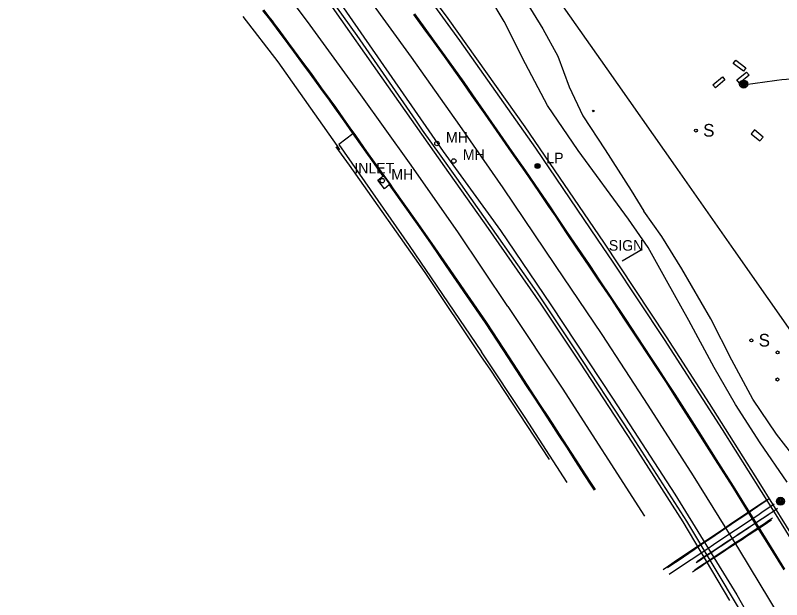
# Model space of a CAD drawing. Extents: x 368532 to 392481, y 10654822 to 10676899.
# Drawn here: x 370545.2 to 370907.9, y 10674120.6 to 10674397.3 of the extents above; entities that cross this region are included whole.
import ezdxf

# ---------------------------------------------------------------- set-up
doc = ezdxf.new("R2010")
doc.units = 0
for name, color, linetype in [('p_Catenary', 7, 'Continuous'), ('p_drainage inlet', 7, 'Continuous'), ('p_dtm sidewalk', 7, 'Continuous'), ('p_railroad rr control', 7, 'Continuous'), ('p_road - paved curb', 7, 'Continuous'), ('p_road conc barrier', 7, 'Continuous'), ('p_road dirt road', 7, 'Continuous'), ('p_road guard rails', 7, 'Continuous'), ('p_road paint stripe', 7, 'Continuous'), ('p_structure sign', 7, 'Continuous'), ('p_structure unidentified', 7, 'Continuous'), ('p_utility general pole', 7, 'Continuous'), ('p_utility manhole', 7, 'Continuous')]:
    doc.layers.add(name, color=color, linetype=linetype)

msp = doc.modelspace()

# ---------------------------------------------------------------- linework, layer by layer
at = {"layer": 'p_Catenary'}
for points in [[(370889.62, 10674364.43), (370891.92, 10674364.73), (370894.21, 10674365.03), (370896.51, 10674365.34), (370898.8, 10674365.64), (370901.1, 10674365.94), (370903.39, 10674366.25), (370905.69, 10674366.55), (370907.98, 10674366.85), (370910.28, 10674367.16), (370912.57, 10674367.46), (370914.87, 10674367.76), (370917.17, 10674368.07), (370919.46, 10674368.37), (370921.76, 10674368.67), (370924.05, 10674368.98), (370926.35, 10674369.28), (370928.64, 10674369.58), (370930.94, 10674369.89), (370933.23, 10674370.19)], [(370851.8, 10674134.93), (370854.4, 10674136.69), (370857.01, 10674138.44), (370859.61, 10674140.19), (370862.22, 10674141.95), (370864.82, 10674143.7), (370867.43, 10674145.45), (370870.03, 10674147.21), (370872.64, 10674148.96), (370875.24, 10674150.72), (370877.85, 10674152.47), (370880.45, 10674154.22), (370883.06, 10674155.98), (370885.67, 10674157.73), (370888.27, 10674159.48), (370890.88, 10674161.24), (370893.48, 10674162.99), (370896.09, 10674164.74), (370898.69, 10674166.5), (370901.3, 10674168.25)], [(370853.83, 10674135.81), (370856.35, 10674137.52), (370858.87, 10674139.22), (370861.39, 10674140.93), (370863.91, 10674142.64), (370866.43, 10674144.35), (370868.95, 10674146.05), (370871.47, 10674147.76), (370874, 10674149.47), (370876.52, 10674151.18), (370879.04, 10674152.88), (370881.56, 10674154.59), (370884.08, 10674156.3), (370886.6, 10674158.01), (370889.12, 10674159.71), (370891.64, 10674161.42), (370894.16, 10674163.13), (370896.68, 10674164.84), (370899.2, 10674166.54), (370901.72, 10674168.25)], [(370854.6, 10674132.63), (370857.22, 10674134.38), (370859.85, 10674136.13), (370862.47, 10674137.89), (370865.09, 10674139.64), (370867.72, 10674141.39), (370870.34, 10674143.15), (370872.96, 10674144.9), (370875.59, 10674146.65), (370878.21, 10674148.41), (370880.84, 10674150.16), (370883.46, 10674151.91), (370886.08, 10674153.67), (370888.71, 10674155.42), (370891.33, 10674157.17), (370893.95, 10674158.92), (370896.58, 10674160.68), (370899.2, 10674162.43), (370901.83, 10674164.18), (370904.45, 10674165.94)], [(370867.41, 10674138.2), (370869.44, 10674139.54), (370871.46, 10674140.88), (370873.48, 10674142.22), (370875.5, 10674143.57), (370877.53, 10674144.91), (370879.55, 10674146.25), (370881.57, 10674147.59), (370883.59, 10674148.94), (370885.61, 10674150.28), (370887.64, 10674151.62), (370889.66, 10674152.96), (370891.68, 10674154.31), (370893.7, 10674155.65), (370895.73, 10674156.99), (370897.75, 10674158.33), (370899.77, 10674159.68), (370901.79, 10674161.02), (370903.82, 10674162.36), (370905.84, 10674163.7)], [(370867.72, 10674138.62), (370869.74, 10674139.95), (370871.75, 10674141.28), (370873.77, 10674142.61), (370875.78, 10674143.94), (370877.8, 10674145.27), (370879.81, 10674146.6), (370881.83, 10674147.93), (370883.84, 10674149.25), (370885.86, 10674150.58), (370887.88, 10674151.91), (370889.89, 10674153.24), (370891.91, 10674154.57), (370893.92, 10674155.9), (370895.94, 10674157.23), (370897.95, 10674158.56), (370899.97, 10674159.89), (370901.99, 10674161.22), (370904, 10674162.55), (370906.02, 10674163.88)], [(370866.64, 10674134.64), (370868.59, 10674135.94), (370870.53, 10674137.24), (370872.48, 10674138.54), (370874.43, 10674139.84), (370876.37, 10674141.14), (370878.32, 10674142.44), (370880.27, 10674143.74), (370882.21, 10674145.04), (370884.16, 10674146.34), (370886.11, 10674147.64), (370888.05, 10674148.94), (370890, 10674150.24), (370891.95, 10674151.53), (370893.89, 10674152.83), (370895.84, 10674154.13), (370897.79, 10674155.43), (370899.73, 10674156.73), (370901.68, 10674158.03), (370903.63, 10674159.33)], [(370865.72, 10674133.76), (370867.69, 10674135.05), (370869.66, 10674136.35), (370871.63, 10674137.65), (370873.6, 10674138.94), (370875.57, 10674140.24), (370877.54, 10674141.53), (370879.51, 10674142.83), (370881.48, 10674144.12), (370883.45, 10674145.42), (370885.42, 10674146.71), (370887.39, 10674148.01), (370889.35, 10674149.3), (370891.32, 10674150.6), (370893.29, 10674151.9), (370895.26, 10674153.19), (370897.23, 10674154.49), (370899.2, 10674155.78), (370901.17, 10674157.08), (370903.14, 10674158.37)]]:
    msp.add_lwpolyline(points, dxfattribs=at)
at = {"layer": 'p_drainage inlet'}
for p, q in [((370716.82, 10674319.32), (370719.2, 10674321.11)), ((370719.86, 10674315.21), (370716.82, 10674319.32)), ((370719.2, 10674321.11), (370719.49, 10674321.31)), ((370719.49, 10674321.31), (370719.61, 10674321.4)), ((370719.49, 10674321.31), (370722.4, 10674317.26)), ((370722.12, 10674317.06), (370719.86, 10674315.21)), ((370722.4, 10674317.26), (370722.12, 10674317.06)), ((370722.4, 10674317.26), (370722.53, 10674317.35))]:
    msp.add_line(p, q, dxfattribs=at)
at = {"layer": 'p_dtm sidewalk'}
for p, q in [((370755.52, 10674385.45), (370717.25, 10674438.01)), ((370791.51, 10674334.39), (370755.52, 10674385.45)), ((370704.96, 10674341.16), (370698.28, 10674336.12)), ((370698.28, 10674336.12), (370731.66, 10674288.32)), ((370820.7, 10674291.32), (370791.51, 10674334.39)), ((370828.14, 10674280.38), (370820.7, 10674291.32)), ((370731.66, 10674288.32), (370765.85, 10674237.98)), ((370852.51, 10674243.75), (370828.14, 10674280.38)), ((370879.96, 10674201.22), (370852.51, 10674243.75)), ((370786.47, 10674206.89), (370765.85, 10674237.98)), ((370806.46, 10674176.11), (370786.47, 10674206.89)), ((370904.59, 10674162.07), (370879.96, 10674201.22)), ((370927.33, 10674124.84), (370904.59, 10674162.07))]:
    msp.add_line(p, q, dxfattribs=at)
at = {"layer": 'p_railroad rr control'}
for points in [[(370857.7, 10674325.96), (370825.29, 10674372.03), (370785.06, 10674429.25), (370743.67, 10674488.23), (370705.22, 10674542.98), (370668.52, 10674595.11), (370628.47, 10674651.67), (370587.92, 10674709.74), (370548.91, 10674764.7), (370545.17, 10674770.04)], [(371121.64, 10673939.77), (371094.86, 10673983.41), (371066.28, 10674027.4), (371041.68, 10674063.49), (371026.94, 10674085.12), (371005.22, 10674117.09), (370994.49, 10674132.1), (370964.03, 10674174.34), (370939.37, 10674209.22), (370917.74, 10674239.94), (370885.32, 10674286.37), (370857.7, 10674325.96)]]:
    msp.add_lwpolyline(points, dxfattribs=at)
at = {"layer": 'p_road - paved curb'}
for p, q in [((370698.05, 10674404.45), (370728.73, 10674360.2)), ((370662.21, 10674399.61), (370664.78, 10674396.32)), ((370662.48, 10674399.83), (370665.05, 10674396.54)), ((370662.6, 10674399.92), (370665.17, 10674396.63)), ((370718.75, 10674367.74), (370695.36, 10674401.2)), ((370664.78, 10674396.32), (370666.32, 10674394.36)), ((370665.05, 10674396.54), (370666.59, 10674394.58)), ((370665.17, 10674396.63), (370666.71, 10674394.67)), ((370666.71, 10674394.67), (370667.76, 10674393.34)), ((370738.85, 10674391.04), (370733.95, 10674397.86)), ((370739.14, 10674391.24), (370734.24, 10674398.06)), ((370666.32, 10674394.36), (370667.36, 10674393.04)), ((370666.59, 10674394.58), (370667.64, 10674393.25)), ((370667.36, 10674393.04), (370669.45, 10674390.19)), ((370667.64, 10674393.25), (370669.73, 10674390.4)), ((370667.76, 10674393.34), (370669.85, 10674390.49)), ((370743.32, 10674384.82), (370738.85, 10674391.04)), ((370743.61, 10674385.02), (370739.14, 10674391.24)), ((370669.45, 10674390.19), (370671.53, 10674387.37)), ((370669.73, 10674390.4), (370671.81, 10674387.58)), ((370669.85, 10674390.49), (370671.93, 10674387.67)), ((370671.81, 10674387.58), (370674.39, 10674384.08)), ((370671.93, 10674387.67), (370674.51, 10674384.17)), ((370671.53, 10674387.37), (370674.11, 10674383.87)), ((370674.11, 10674383.87), (370676.79, 10674380.19)), ((370674.39, 10674384.08), (370677.07, 10674380.39)), ((370674.51, 10674384.17), (370677.19, 10674380.48)), ((370748.37, 10674377.86), (370743.32, 10674384.82)), ((370748.66, 10674378.06), (370743.61, 10674385.02)), ((370676.79, 10674380.19), (370680.67, 10674374.9)), ((370677.07, 10674380.39), (370680.95, 10674375.11)), ((370677.19, 10674380.48), (370681.07, 10674375.2)), ((370757.33, 10674365.4), (370748.37, 10674377.86)), ((370757.62, 10674365.6), (370748.66, 10674378.06)), ((370680.67, 10674374.9), (370684.75, 10674369.39)), ((370680.95, 10674375.11), (370685.03, 10674369.6)), ((370681.07, 10674375.2), (370685.15, 10674369.69)), ((370684.75, 10674369.39), (370689.59, 10674362.74)), ((370685.03, 10674369.6), (370689.87, 10674362.95)), ((370685.15, 10674369.69), (370689.99, 10674363.04)), ((370748.51, 10674325.6), (370718.75, 10674367.74)), ((370689.59, 10674362.74), (370693.7, 10674357.18)), ((370689.87, 10674362.95), (370693.98, 10674357.38)), ((370689.99, 10674363.04), (370694.1, 10674357.47)), ((370761.43, 10674359.43), (370757.33, 10674365.4)), ((370761.72, 10674359.62), (370757.62, 10674365.6)), ((370728.73, 10674360.2), (370747.67, 10674332.82)), ((370767.63, 10674350.56), (370761.43, 10674359.43)), ((370767.92, 10674350.76), (370761.72, 10674359.62)), ((370693.7, 10674357.18), (370696.3, 10674353.51)), ((370693.98, 10674357.38), (370696.59, 10674353.71)), ((370694.1, 10674357.47), (370696.71, 10674353.8)), ((370696.3, 10674353.51), (370699.82, 10674348.49)), ((370696.59, 10674353.71), (370700.11, 10674348.69)), ((370696.71, 10674353.8), (370700.23, 10674348.78)), ((370699.82, 10674348.49), (370703.17, 10674343.79)), ((370700.11, 10674348.69), (370703.46, 10674343.99)), ((370700.23, 10674348.78), (370703.58, 10674344.08)), ((370774.44, 10674340.83), (370767.63, 10674350.56)), ((370774.73, 10674341.03), (370767.92, 10674350.76)), ((370703.46, 10674343.99), (370706.05, 10674340.3)), ((370703.58, 10674344.08), (370706.17, 10674340.39)), ((370703.17, 10674343.79), (370705.76, 10674340.1)), ((370706.05, 10674340.3), (370711.35, 10674332.74)), ((370706.17, 10674340.39), (370711.47, 10674332.83)), ((370780.09, 10674332.65), (370774.44, 10674340.83)), ((370780.38, 10674332.85), (370774.73, 10674341.03)), ((370705.76, 10674340.1), (370711.06, 10674332.54)), ((370711.06, 10674332.54), (370714.65, 10674327.49)), ((370711.35, 10674332.74), (370714.94, 10674327.69)), ((370711.47, 10674332.83), (370715.06, 10674327.78)), ((370747.67, 10674332.82), (370774.87, 10674295.39)), ((370786.58, 10674323.4), (370780.09, 10674332.65)), ((370786.87, 10674323.6), (370780.38, 10674332.85)), ((370714.65, 10674327.49), (370717.12, 10674324)), ((370714.94, 10674327.69), (370717.41, 10674324.2)), ((370715.06, 10674327.78), (370717.53, 10674324.29)), ((370717.12, 10674324), (370719.2, 10674321.11)), ((370717.41, 10674324.2), (370719.49, 10674321.31)), ((370717.53, 10674324.29), (370719.61, 10674321.4)), ((370769.1, 10674296.37), (370748.51, 10674325.6)), ((370793.07, 10674314.04), (370786.58, 10674323.4)), ((370793.36, 10674314.24), (370786.87, 10674323.6)), ((370719.61, 10674321.4), (370722.53, 10674317.35)), ((370722.12, 10674317.06), (370723.67, 10674314.9)), ((370722.4, 10674317.26), (370723.96, 10674315.1)), ((370722.53, 10674317.35), (370724.08, 10674315.19)), ((370723.67, 10674314.9), (370728.74, 10674307.74)), ((370723.96, 10674315.1), (370729.03, 10674307.94)), ((370724.08, 10674315.19), (370729.15, 10674308.03)), ((370797.85, 10674306.94), (370793.07, 10674314.04)), ((370798.14, 10674307.14), (370793.36, 10674314.24)), ((370728.74, 10674307.74), (370735.35, 10674298.39)), ((370729.03, 10674307.94), (370735.64, 10674298.59)), ((370729.15, 10674308.03), (370735.76, 10674298.68)), ((370800.91, 10674302.39), (370797.85, 10674306.94)), ((370801.21, 10674302.59), (370798.14, 10674307.14)), ((370806.25, 10674294.34), (370800.91, 10674302.39)), ((370806.54, 10674294.54), (370801.21, 10674302.59)), ((370735.35, 10674298.39), (370741.94, 10674288.91)), ((370735.64, 10674298.59), (370742.23, 10674289.1)), ((370735.76, 10674298.68), (370742.35, 10674289.19)), ((370794.14, 10674260.51), (370769.1, 10674296.37)), ((370774.87, 10674295.39), (370798.73, 10674260.18)), ((370811.11, 10674287.21), (370806.25, 10674294.34)), ((370811.4, 10674287.41), (370806.54, 10674294.54)), ((370741.94, 10674288.91), (370749.01, 10674278.68)), ((370742.23, 10674289.1), (370749.3, 10674278.87)), ((370742.35, 10674289.19), (370749.42, 10674278.96)), ((370816.96, 10674278.62), (370811.11, 10674287.21)), ((370817.25, 10674278.82), (370811.4, 10674287.41)), ((370749.01, 10674278.68), (370758.73, 10674264.55)), ((370749.3, 10674278.87), (370759.02, 10674264.75)), ((370749.42, 10674278.96), (370759.14, 10674264.83)), ((370821.42, 10674271.93), (370816.96, 10674278.62)), ((370821.72, 10674272.13), (370817.25, 10674278.82)), ((370827.3, 10674263.24), (370821.42, 10674271.93)), ((370827.6, 10674263.44), (370821.72, 10674272.13)), ((370758.73, 10674264.55), (370767.56, 10674251.65)), ((370759.02, 10674264.75), (370767.85, 10674251.85)), ((370759.14, 10674264.83), (370767.97, 10674251.93)), ((370812.34, 10674233.04), (370794.14, 10674260.51)), ((370833.68, 10674253.58), (370827.3, 10674263.24)), ((370833.97, 10674253.77), (370827.6, 10674263.44)), ((370798.73, 10674260.18), (370828.13, 10674215.49)), ((370839.36, 10674244.91), (370833.68, 10674253.58)), ((370839.65, 10674245.1), (370833.97, 10674253.77)), ((370767.56, 10674251.65), (370775.96, 10674238.97)), ((370767.85, 10674251.85), (370776.25, 10674239.16)), ((370767.97, 10674251.93), (370776.38, 10674239.24)), ((370845.75, 10674235.25), (370839.36, 10674244.91)), ((370846.04, 10674235.44), (370839.65, 10674245.1)), ((370775.96, 10674238.97), (370782.47, 10674228.93)), ((370776.25, 10674239.16), (370782.76, 10674229.12)), ((370776.38, 10674239.24), (370782.89, 10674229.2)), ((370848.81, 10674230.56), (370845.75, 10674235.25)), ((370849.1, 10674230.75), (370846.04, 10674235.44)), ((370837.55, 10674194.66), (370812.34, 10674233.04)), ((370782.47, 10674228.93), (370787.04, 10674221.9)), ((370782.76, 10674229.12), (370787.33, 10674222.09)), ((370782.89, 10674229.2), (370787.46, 10674222.17)), ((370853.49, 10674223.48), (370848.81, 10674230.56)), ((370853.78, 10674223.67), (370849.1, 10674230.75)), ((370787.04, 10674221.9), (370790.54, 10674216.54)), ((370787.33, 10674222.09), (370790.83, 10674216.73)), ((370787.46, 10674222.17), (370790.96, 10674216.81)), ((370857.2, 10674217.65), (370853.49, 10674223.48)), ((370857.49, 10674217.84), (370853.78, 10674223.67)), ((370868.52, 10674199.82), (370857.2, 10674217.65)), ((370868.81, 10674200.01), (370857.49, 10674217.84)), ((370790.54, 10674216.54), (370793.58, 10674211.92)), ((370790.83, 10674216.73), (370793.87, 10674212.11)), ((370790.96, 10674216.81), (370794, 10674212.19)), ((370828.13, 10674215.49), (370857.31, 10674170.48)), ((370793.58, 10674211.92), (370796.49, 10674207.49)), ((370793.87, 10674212.11), (370796.78, 10674207.68)), ((370794, 10674212.19), (370796.91, 10674207.76)), ((370796.49, 10674207.49), (370798.82, 10674203.89)), ((370796.78, 10674207.68), (370799.11, 10674204.08)), ((370796.91, 10674207.76), (370799.24, 10674204.16)), ((370798.82, 10674203.89), (370802.19, 10674198.68)), ((370799.11, 10674204.08), (370802.48, 10674198.87)), ((370799.24, 10674204.16), (370802.61, 10674198.95)), ((370802.48, 10674198.87), (370806.31, 10674193.01)), ((370802.61, 10674198.95), (370806.44, 10674193.09)), ((370877.89, 10674185.1), (370868.52, 10674199.82)), ((370878.18, 10674185.29), (370868.81, 10674200.01)), ((370802.19, 10674198.68), (370806.02, 10674192.82)), ((370806.02, 10674192.82), (370810.04, 10674186.55)), ((370806.31, 10674193.01), (370810.33, 10674186.74)), ((370806.44, 10674193.09), (370810.46, 10674186.82)), ((370861.3, 10674157.46), (370837.55, 10674194.66)), ((370810.04, 10674186.55), (370814.65, 10674179.42)), ((370810.33, 10674186.74), (370814.94, 10674179.61)), ((370810.46, 10674186.82), (370815.07, 10674179.69)), ((370884.9, 10674174.11), (370877.89, 10674185.1)), ((370885.19, 10674174.3), (370878.18, 10674185.29)), ((370814.65, 10674179.42), (370817.34, 10674175.37)), ((370814.94, 10674179.61), (370817.63, 10674175.56)), ((370815.07, 10674179.69), (370817.76, 10674175.64)), ((370817.34, 10674175.37), (370819.19, 10674172.47)), ((370817.63, 10674175.56), (370819.48, 10674172.66)), ((370817.76, 10674175.64), (370819.61, 10674172.74)), ((370895.87, 10674156.33), (370884.9, 10674174.11)), ((370896.16, 10674156.51), (370885.19, 10674174.3)), ((370857.31, 10674170.48), (370886.7, 10674122.96)), ((370883.34, 10674120.16), (370861.3, 10674157.46)), ((370902.82, 10674145.2), (370895.87, 10674156.33)), ((370903.12, 10674145.38), (370896.16, 10674156.51)), ((370909.17, 10674134.83), (370902.82, 10674145.2)), ((370909.46, 10674135.01), (370903.12, 10674145.38)), ((370886.7, 10674122.96), (370909.43, 10674083.18))]:
    msp.add_line(p, q, dxfattribs=at)
msp.add_lwpolyline([(370909.04, 10674134.75), (370902.69, 10674145.12), (370895.74, 10674156.25), (370884.77, 10674174.03), (370877.76, 10674185.02), (370868.39, 10674199.74), (370857.07, 10674217.57), (370853.36, 10674223.4), (370848.68, 10674230.48), (370845.62, 10674235.17), (370839.23, 10674244.83), (370833.55, 10674253.5), (370827.18, 10674263.16), (370821.3, 10674271.85), (370816.84, 10674278.54), (370810.99, 10674287.13), (370806.13, 10674294.26), (370800.79, 10674302.31), (370797.73, 10674306.86), (370792.95, 10674313.96), (370786.46, 10674323.31), (370779.97, 10674332.56), (370774.32, 10674340.74), (370767.51, 10674350.47), (370761.31, 10674359.34), (370757.21, 10674365.31), (370748.25, 10674377.77), (370743.2, 10674384.73), (370738.73, 10674390.95), (370733.83, 10674397.77)], dxfattribs=at)
at = {"layer": 'p_road conc barrier'}
for p, q in [((370726.3, 10674428.07), (370749.87, 10674395.8)), ((370707.03, 10674387.77), (370679.13, 10674426.42)), ((370749.87, 10674395.8), (370786.32, 10674344.45)), ((370734.81, 10674347.63), (370707.03, 10674387.77)), ((370885.03, 10674374.47), (370886.22, 10674376.03)), ((370889.79, 10674370.84), (370885.03, 10674374.47)), ((370886.22, 10674376.03), (370890.98, 10674372.41)), ((370886.65, 10674366.75), (370891.33, 10674370.46)), ((370890.98, 10674372.41), (370889.79, 10674370.84)), ((370891.33, 10674370.46), (370892.57, 10674368.9)), ((370875.37, 10674364.35), (370879.89, 10674368.17)), ((370881.07, 10674366.78), (370876.55, 10674362.96)), ((370879.89, 10674368.17), (370881.07, 10674366.78)), ((370887.89, 10674365.19), (370886.65, 10674366.75)), ((370892.57, 10674368.9), (370887.89, 10674365.19)), ((370876.55, 10674362.96), (370875.37, 10674364.35)), ((370737.9, 10674342.86), (370734.81, 10674347.63)), ((370786.32, 10674344.45), (370823.53, 10674289.93)), ((370746.79, 10674330.61), (370737.9, 10674342.86)), ((370895, 10674343.04), (370893.47, 10674341.18)), ((370893.47, 10674341.18), (370897.6, 10674337.81)), ((370899.13, 10674339.67), (370895, 10674343.04)), ((370897.6, 10674337.81), (370899.13, 10674339.67)), ((370703.38, 10674326.43), (370697.07, 10674335.1)), ((370754.11, 10674320.25), (370746.79, 10674330.61)), ((370739.1, 10674275.5), (370703.38, 10674326.43)), ((370761.01, 10674310.56), (370754.11, 10674320.25)), ((370792.1, 10674266.32), (370761.01, 10674310.56)), ((370823.53, 10674289.93), (370853.24, 10674244.99)), ((370765.87, 10674235.66), (370739.1, 10674275.5)), ((370810.4, 10674238.96), (370792.1, 10674266.32)), ((370853.24, 10674244.99), (370873.55, 10674213.51)), ((370836.03, 10674199.8), (370810.4, 10674238.96)), ((370769.88, 10674229.82), (370765.87, 10674235.66)), ((370797.98, 10674187.03), (370769.88, 10674229.82)), ((370873.55, 10674213.51), (370897.17, 10674176.17)), ((370863.03, 10674157.7), (370836.03, 10674199.8)), ((370897.17, 10674176.17), (370918.76, 10674141.26)), ((370888.45, 10674115.35), (370863.03, 10674157.7))]:
    msp.add_line(p, q, dxfattribs=at)
at = {"layer": 'p_road dirt road'}
for p, q in [((370776.55, 10674394.34), (370766.13, 10674412.07)), ((370785.12, 10674406.95), (370794.83, 10674390.98)), ((370786.71, 10674374.38), (370776.55, 10674394.34)), ((370794.83, 10674390.98), (370801.93, 10674378.04)), ((370801.93, 10674378.04), (370807.32, 10674363.48)), ((370797.12, 10674354.64), (370786.71, 10674374.38)), ((370807.32, 10674363.48), (370813.86, 10674349.64)), ((370811.67, 10674333.26), (370797.12, 10674354.64)), ((370813.86, 10674349.64), (370824.33, 10674333.69)), ((370835.44, 10674300.85), (370811.67, 10674333.26)), ((370824.33, 10674333.69), (370836.61, 10674314.32)), ((370836.61, 10674314.32), (370842.67, 10674304.57)), ((370851.23, 10674292.57), (370842.67, 10674304.57)), ((370844.78, 10674287.35), (370835.44, 10674300.85)), ((370860.71, 10674277.2), (370851.23, 10674292.57)), ((370853.48, 10674271.76), (370844.78, 10674287.35)), ((370874.34, 10674253.62), (370860.71, 10674277.2)), ((370864.03, 10674252.78), (370853.48, 10674271.76)), ((370884.35, 10674233.94), (370874.34, 10674253.62)), ((370875.98, 10674230.47), (370864.03, 10674252.78)), ((370894.28, 10674215.56), (370884.35, 10674233.94)), ((370886.06, 10674212.99), (370875.98, 10674230.47)), ((370905.52, 10674198.94), (370894.28, 10674215.56)), ((370897.77, 10674194.84), (370886.06, 10674212.99)), ((370915.98, 10674185.4), (370905.52, 10674198.94)), ((370910.51, 10674176.3), (370897.77, 10674194.84))]:
    msp.add_line(p, q, dxfattribs=at)
at = {"layer": 'p_road guard rails'}
for p, q in [((370652.8, 10674396.78), (370669.4, 10674375.31)), ((370669.4, 10674375.31), (370697.43, 10674335.68)), ((370697.43, 10674335.68), (370698.56, 10674333.67))]:
    msp.add_line(p, q, dxfattribs=at)
at = {"layer": 'p_road paint stripe'}
for p, q in [((370684.75, 10674392.68), (370661.38, 10674423.86)), ((370708.88, 10674410.1), (370732.53, 10674377.57)), ((370708.66, 10674359.74), (370684.75, 10674392.68)), ((370732.53, 10674377.57), (370755.46, 10674345.07)), ((370731.72, 10674327.53), (370708.66, 10674359.74)), ((370755.46, 10674345.07), (370775.98, 10674315.62)), ((370754.59, 10674294.71), (370731.72, 10674327.53)), ((370775.98, 10674315.62), (370800.72, 10674278.9)), ((370778.35, 10674259.39), (370754.59, 10674294.71)), ((370800.72, 10674278.9), (370822.82, 10674246.21)), ((370778.35, 10674259.39), (370803.95, 10674220.83)), ((370822.82, 10674246.21), (370844.62, 10674212.67)), ((370803.95, 10674220.83), (370843.06, 10674160.07)), ((370844.62, 10674212.67), (370866.04, 10674179.18)), ((370866.04, 10674179.18), (370887.49, 10674144.6)), ((370887.49, 10674144.6), (370907.81, 10674111.18))]:
    msp.add_line(p, q, dxfattribs=at)
at = {"layer": 'p_structure sign'}
msp.add_lwpolyline([(370832.37, 10674281.07), (370841.9, 10674286.64)], dxfattribs=at)
for centre in [(370867.3, 10674342.76), (370893.58, 10674243.37), (370905.97, 10674237.65), (370905.93, 10674224.86)]:
    msp.add_circle(centre, 0.713, dxfattribs=at)
at = {"layer": 'p_structure unidentified'}
msp.add_circle((370818.74, 10674352.05), 0.375, dxfattribs=at)
at = {"layer": 'p_utility general pole'}
for centre, radius in [((370889.93, 10674364.74), 1.9), ((370889.93, 10674364.74), 1.44), ((370889.93, 10674364.74), 0.973), ((370889.93, 10674364.74), 0.539), ((370889.93, 10674364.74), 0.192), ((370792.38, 10674325.97), 1.19), ((370792.38, 10674325.97), 0.901), ((370792.38, 10674325.97), 0.608), ((370792.38, 10674325.97), 0.337), ((370792.38, 10674325.97), 0.12), ((370907.35, 10674167.21), 1.9), ((370907.35, 10674167.21), 1.44), ((370907.35, 10674167.21), 0.973), ((370907.35, 10674167.21), 0.539), ((370907.35, 10674167.21), 0.192)]:
    msp.add_circle(centre, radius, dxfattribs=at)
at = {"layer": 'p_utility manhole'}
for centre in [(370744.73, 10674336.62), (370752.72, 10674328.35), (370718.86, 10674319.03)]:
    msp.add_circle(centre, 1.05, dxfattribs=at)

# ---------------------------------------------------------------- texts
at = {"layer": 'p_drainage inlet'}
msp.add_text(' INLET', height=5, dxfattribs=at).set_placement((370703.76, 10674322.45))
at = {"layer": 'p_structure sign'}
for s, height, p in [('S', 6, (370870.76, 10674339.87)), (' SIGN', 5, (370824.25, 10674285.86)), ('S', 6, (370897.04, 10674240.47))]:
    msp.add_text(s, height=height, dxfattribs=at).set_placement(p)
at = {"layer": 'p_utility general pole'}
msp.add_text('LP', height=5, dxfattribs=at).set_placement((370796.5, 10674327.26))
at = {"layer": 'p_utility manhole'}
for p in [(370749, 10674337.09), (370756.99, 10674328.81), (370723.13, 10674319.49)]:
    msp.add_text('MH', height=5, dxfattribs=at).set_placement(p)

doc.saveas('drawing.dxf')
